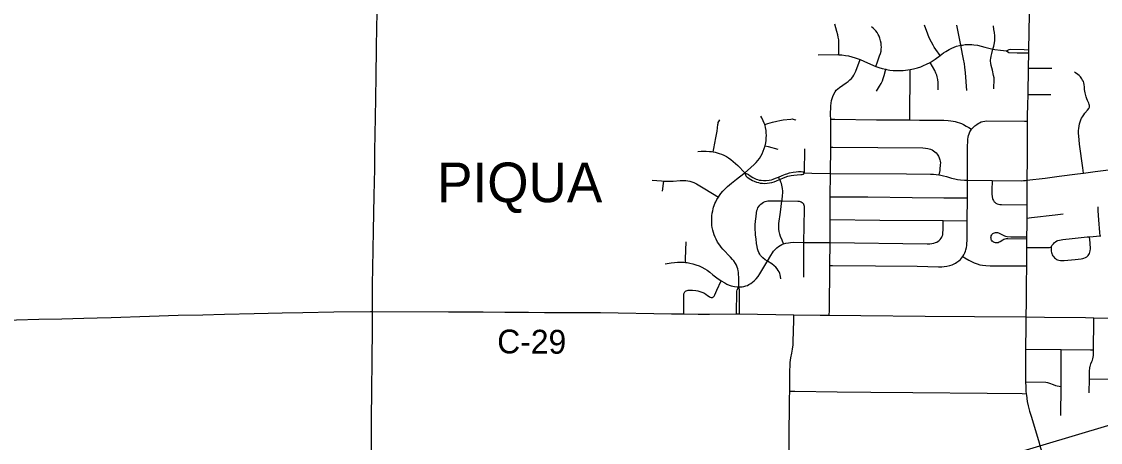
# Model space of a CAD drawing. Extents: x -87 to 2145, y -2128 to 440.
# Drawn here: x 86.3 to 154.2, y -1144.5 to -1118 of the extents above; entities that cross this region are included whole.
import ezdxf

# ---------------------------------------------------------------- set-up
doc = ezdxf.new("R2010")
doc.units = 0
for name, color, linetype in [('GM_X_City_Street', 7, 'Continuous'), ('GM_X_Corporation_Text', 7, 'Continuous'), ('GM_X_County_Road', 7, 'Continuous'), ('GM_X_County_Road_Text', 7, 'Continuous'), ('GM_X_Rail_Line', 7, 'Continuous'), ('GM_X_State_Route', 7, 'Continuous'), ('GM_X_Township_Road', 7, 'Continuous')]:
    doc.layers.add(name, color=color, linetype=linetype)

msp = doc.modelspace()

# ---------------------------------------------------------------- linework, layer by layer
at = {"layer": 'GM_X_City_Street'}
for p, q in [((145.448, -1119.471), (145.198, -1118.209)), ((142.232, -1124.177), (142.259, -1121)), ((135.603, -1127.502), (135.61, -1125.992))]:
    msp.add_line(p, q, dxfattribs=at)
for points in [[(137.759, -1120.066), (137.763, -1119.877), (137.766, -1119.652), (137.761, -1119.341), (137.747, -1119.13), (137.724, -1118.952), (137.693, -1118.808), (137.635, -1118.604), (137.503, -1118.149)], [(140.086, -1120.799), (140.196, -1120.507), (140.327, -1120.144), (140.381, -1119.994), (140.419, -1119.838), (140.432, -1119.721), (140.437, -1119.586), (140.429, -1119.461), (140.416, -1119.333), (140.389, -1119.19), (140.342, -1119.019), (140.297, -1118.898), (140.243, -1118.782), (140.177, -1118.672), (140.094, -1118.562), (140.011, -1118.479), (139.927, -1118.399), (139.82, -1118.312)], [(144.131, -1120.108), (143.855, -1119.731), (143.766, -1119.594), (143.688, -1119.47), (143.589, -1119.282), (143.455, -1119.001), (143.36, -1118.776), (143.144, -1118.206)], [(147.462, -1119.712), (147.524, -1119.524), (147.569, -1119.321), (147.585, -1119.16), (147.589, -1119.031), (147.58, -1118.869), (147.554, -1118.659), (147.523, -1118.481), (147.5, -1118.251)], [(136.449, -1120.065), (137.65, -1120.058), (137.759, -1120.066), (137.945, -1120.08), (138.175, -1120.108), (138.37, -1120.144), (138.578, -1120.195), (138.784, -1120.258), (139.107, -1120.375), (139.337, -1120.47), (139.754, -1120.665), (140.086, -1120.799), (140.272, -1120.864), (140.491, -1120.927), (140.709, -1120.979), (140.761, -1120.992), (140.97, -1121.028), (141.18, -1121.052), (141.376, -1121.062), (141.621, -1121.065), (141.816, -1121.055), (142.092, -1121.026), (142.259, -1121), (142.46, -1120.957), (142.713, -1120.89), (142.913, -1120.822), (143.095, -1120.751), (143.272, -1120.667), (143.501, -1120.546), (143.687, -1120.428), (143.815, -1120.339), (144.131, -1120.108), (144.345, -1119.95), (144.498, -1119.852), (144.713, -1119.729), (144.875, -1119.647), (145.028, -1119.582), (145.17, -1119.535), (145.347, -1119.49), (145.448, -1119.471), (145.542, -1119.454), (145.722, -1119.431), (145.904, -1119.421), (146.136, -1119.423), (146.268, -1119.436), (146.48, -1119.473), (146.722, -1119.524), (146.961, -1119.587), (147.462, -1119.712), (147.582, -1119.742), (147.938, -1119.786), (148.325, -1119.82)], [(145.828, -1122.316), (145.734, -1121.21), (145.698, -1120.852), (145.667, -1120.642), (145.618, -1120.337), (145.553, -1120.029), (145.448, -1119.471)], [(147.511, -1122.213), (147.52, -1122.028), (147.537, -1121.781), (147.54, -1121.638), (147.531, -1121.523), (147.504, -1121.378), (147.43, -1121.041), (147.361, -1120.753), (147.329, -1120.592), (147.316, -1120.477), (147.316, -1120.395), (147.326, -1120.297), (147.354, -1120.152), (147.397, -1119.993), (147.462, -1119.712)], [(148.325, -1119.82), (148.481, -1119.729), (148.563, -1119.721), (149.434, -1119.743), (149.709, -1119.75)], [(148.325, -1119.82), (148.468, -1119.92), (148.982, -1119.938), (149.455, -1119.941), (149.706, -1119.943)], [(137.157, -1136.48), (137.16, -1136.177), (137.187, -1133.356), (137.2, -1131.908), (137.213, -1130.458), (137.216, -1129.013), (137.229, -1127.556), (137.251, -1125.892), (137.242, -1124.131), (137.237, -1123.882), (137.253, -1123.291), (137.27, -1123.11), (137.298, -1122.946), (137.331, -1122.817), (137.369, -1122.707), (137.432, -1122.559), (137.517, -1122.41), (137.597, -1122.308), (137.702, -1122.208), (137.793, -1122.134), (138.219, -1121.837), (138.338, -1121.751), (138.448, -1121.657), (138.551, -1121.554), (138.634, -1121.455), (138.709, -1121.35), (138.774, -1121.236), (138.83, -1121.105), (139.107, -1120.375)], [(140.122, -1122.372), (140.319, -1122.052), (140.414, -1121.879), (140.497, -1121.7), (140.554, -1121.557), (140.611, -1121.372), (140.709, -1120.979)], [(144.003, -1122.286), (144.003, -1121.825), (143.983, -1121.621), (143.952, -1121.462), (143.923, -1121.349), (143.875, -1121.224), (143.796, -1121.059), (143.656, -1120.797), (143.501, -1120.546)], [(149.688, -1120.918), (149.881, -1120.919), (151.174, -1120.922)], [(153.158, -1127.522), (153.115, -1127.186), (152.923, -1125.694), (152.864, -1125.173), (152.849, -1125.026), (152.844, -1124.928), (152.851, -1124.831), (152.862, -1124.712), (152.884, -1124.577), (152.914, -1124.429), (152.949, -1124.299), (153.002, -1124.163), (153.046, -1124.058), (153.095, -1123.972), (153.181, -1123.852), (153.26, -1123.748), (153.411, -1123.554), (153.498, -1123.453), (153.539, -1123.379), (153.553, -1123.319), (153.549, -1123.261), (153.532, -1123.199), (153.495, -1123.108), (153.417, -1122.945), (153.372, -1122.84), (153.331, -1122.715), (153.269, -1122.46), (153.235, -1122.267), (153.219, -1122.104), (153.204, -1121.941), (153.183, -1121.828), (153.157, -1121.751), (153.113, -1121.663), (153.06, -1121.58), (152.967, -1121.466), (152.887, -1121.384), (152.8, -1121.31), (152.653, -1121.206), (152.596, -1121.174)], [(149.658, -1122.568), (149.938, -1122.567), (151.107, -1122.562)], [(131.452, -1134.698), (131.448, -1134.232), (131.427, -1133.775), (131.413, -1133.68), (131.386, -1133.567), (131.351, -1133.456), (131.305, -1133.336), (131.246, -1133.219), (131.139, -1133.056), (131.061, -1132.965), (130.931, -1132.818), (130.452, -1132.323), (130.345, -1132.2), (130.25, -1132.074), (130.123, -1131.877), (130.022, -1131.69), (129.966, -1131.569), (129.905, -1131.412), (129.86, -1131.272), (129.817, -1131.116), (129.786, -1130.951), (129.767, -1130.819), (129.755, -1130.62), (129.754, -1130.406), (129.764, -1130.224), (129.787, -1130.043), (129.814, -1129.901), (129.84, -1129.781), (129.869, -1129.674), (129.907, -1129.562), (129.951, -1129.449), (130.003, -1129.335), (130.078, -1129.192), (130.168, -1129.049), (130.237, -1128.946), (130.332, -1128.817), (130.458, -1128.664), (130.616, -1128.495), (130.747, -1128.369), (130.985, -1128.166), (131.308, -1127.912), (131.771, -1127.546), (131.828, -1127.499), (132.188, -1127.201), (132.443, -1126.972), (132.557, -1126.856), (132.661, -1126.732), (132.757, -1126.598), (132.845, -1126.458), (132.923, -1126.311), (132.998, -1126.143), (133.061, -1125.969), (133.111, -1125.799), (133.152, -1125.611), (133.174, -1125.461), (133.187, -1125.312), (133.192, -1125.163), (133.186, -1124.982), (133.171, -1124.835), (133.141, -1124.659), (133.107, -1124.517), (133.089, -1124.462), (133.062, -1124.379), (132.999, -1124.229), (132.904, -1124.04), (132.849, -1123.939)], [(129.846, -1126.19), (129.884, -1125.985), (130.012, -1125.293), (130.087, -1124.891), (130.133, -1124.468), (130.145, -1124.404), (130.163, -1124.342), (130.191, -1124.282), (130.256, -1124.169)], [(133.089, -1124.462), (133.275, -1124.403), (133.584, -1124.312), (133.844, -1124.247), (134.036, -1124.204), (134.254, -1124.165), (134.737, -1124.118), (134.819, -1124.114), (134.884, -1124.12), (134.947, -1124.137), (135.036, -1124.178), (135.051, -1124.185)], [(137.242, -1124.131), (137.512, -1124.134), (140.138, -1124.16), (142.232, -1124.177), (142.845, -1124.181), (144.378, -1124.186), (144.651, -1124.204), (144.816, -1124.221), (144.947, -1124.243), (145.09, -1124.273), (145.218, -1124.311), (145.361, -1124.355), (145.489, -1124.407), (145.618, -1124.471), (145.784, -1124.564), (145.942, -1124.658), (146.116, -1124.767)], [(146.116, -1124.767), (146.233, -1124.632), (146.321, -1124.555), (146.438, -1124.461), (146.534, -1124.395), (146.624, -1124.347), (146.727, -1124.302), (146.827, -1124.272), (146.961, -1124.251), (147.078, -1124.24), (149.443, -1124.251), (149.626, -1124.251)], [(145.562, -1132.791), (145.636, -1132.669), (145.688, -1132.561), (145.732, -1132.444), (145.761, -1132.359), (145.794, -1132.217), (145.813, -1132.089), (145.827, -1131.944), (145.838, -1131.794), (145.844, -1130.543), (145.851, -1129.084), (145.853, -1128.662), (145.864, -1127.971), (145.869, -1127.696), (145.865, -1125.972), (145.889, -1125.396), (145.904, -1125.264), (145.927, -1125.166), (145.965, -1125.055), (146.016, -1124.932), (146.059, -1124.854), (146.116, -1124.767)], [(133.111, -1125.799), (133.314, -1125.853), (133.909, -1126.01)], [(137.251, -1125.892), (137.385, -1125.893), (143.049, -1125.941), (143.214, -1125.949), (143.357, -1125.967), (143.449, -1125.988), (143.531, -1126.019), (143.627, -1126.067), (143.718, -1126.127), (143.8, -1126.184), (143.882, -1126.258), (143.949, -1126.325), (143.997, -1126.388), (144.037, -1126.456), (144.082, -1126.559), (144.127, -1126.696), (144.143, -1126.773), (144.15, -1126.869), (144.147, -1127.014), (144.123, -1127.274), (144.107, -1127.368), (144.064, -1127.631)], [(128.877, -1126.163), (129.089, -1126.148), (129.238, -1126.139), (129.404, -1126.142), (129.608, -1126.157), (129.738, -1126.174), (129.846, -1126.19), (129.966, -1126.213), (130.09, -1126.242), (130.218, -1126.281), (130.375, -1126.336), (130.512, -1126.396), (130.604, -1126.437), (130.688, -1126.486), (130.815, -1126.567), (130.952, -1126.661), (131.108, -1126.784), (131.256, -1126.916), (131.396, -1127.057), (131.828, -1127.499)], [(126.002, -1127.963), (126.581, -1128.021), (126.736, -1128.035), (127.034, -1128.039), (127.33, -1128.028), (127.756, -1127.997), (127.918, -1127.992), (128.113, -1128), (128.242, -1128.015), (128.369, -1128.039), (128.493, -1128.074), (128.63, -1128.126), (128.792, -1128.199), (128.906, -1128.261), (129.324, -1128.521), (130.168, -1129.049)], [(131.828, -1127.499), (132.061, -1127.609), (132.18, -1127.697), (132.345, -1127.804), (132.46, -1127.868), (132.55, -1127.908), (132.627, -1127.934), (132.739, -1127.961), (132.869, -1127.978), (133.017, -1127.986), (133.181, -1127.982), (133.377, -1127.964), (133.507, -1127.943), (133.617, -1127.912), (133.771, -1127.855), (133.948, -1127.777), (134.177, -1127.676), (134.291, -1127.626), (134.395, -1127.59), (134.483, -1127.564), (134.657, -1127.518), (134.882, -1127.471), (135.061, -1127.444), (135.224, -1127.432), (135.387, -1127.435), (135.499, -1127.443), (135.603, -1127.502)], [(131.828, -1127.499), (131.891, -1127.708), (131.987, -1127.79), (132.207, -1127.933), (132.322, -1127.996), (132.427, -1128.043), (132.566, -1128.092), (132.692, -1128.128), (132.805, -1128.15), (132.952, -1128.167), (133.099, -1128.172), (133.247, -1128.166), (133.393, -1128.148), (133.538, -1128.118), (133.679, -1128.076), (133.832, -1128.018), (134.028, -1127.928), (134.233, -1127.843), (134.38, -1127.784), (134.553, -1127.725), (134.745, -1127.68), (134.913, -1127.652), (135.125, -1127.63), (135.366, -1127.619), (135.453, -1127.613), (135.529, -1127.589), (135.603, -1127.502)], [(134.28, -1131.99), (134.183, -1131.745), (134.092, -1131.515), (134.048, -1131.372), (134.008, -1131.216), (133.982, -1131.063), (133.973, -1130.931), (133.972, -1130.83), (133.984, -1130.697), (134.077, -1129.997), (134.176, -1129.28), (134.185, -1129.216), (134.213, -1128.94), (134.222, -1128.778), (134.219, -1128.665), (134.21, -1128.505), (134.193, -1128.394), (134.17, -1128.294), (134.141, -1128.183), (134.106, -1128.091), (134.053, -1127.977), (134.028, -1127.928), (133.988, -1127.85), (133.948, -1127.777)], [(135.603, -1127.502), (136.046, -1127.538), (137.229, -1127.556), (142.01, -1127.577), (143.52, -1127.594), (143.728, -1127.596), (143.894, -1127.61), (144.064, -1127.631), (144.19, -1127.655), (144.346, -1127.694), (144.544, -1127.748), (144.858, -1127.841), (145.063, -1127.893), (145.239, -1127.925), (145.417, -1127.947), (145.678, -1127.964), (145.864, -1127.971), (147.405, -1127.996), (149.234, -1128.008), (149.386, -1127.999), (149.51, -1127.987), (149.606, -1127.973)], [(147.405, -1127.996), (147.391, -1128.626), (147.394, -1128.827), (147.409, -1129.017), (147.429, -1129.117), (147.453, -1129.182), (147.489, -1129.254), (147.542, -1129.328), (147.579, -1129.366), (147.653, -1129.416), (147.727, -1129.453), (147.808, -1129.482), (147.904, -1129.498), (148.004, -1129.507), (149.599, -1129.516)], [(126.648, -1128.672), (126.714, -1128.191), (126.736, -1128.035)], [(133.256, -1133.076), (133.123, -1132.986), (132.97, -1132.861), (132.897, -1132.795), (132.832, -1132.721), (132.776, -1132.645), (132.723, -1132.539), (132.674, -1132.417), (132.635, -1132.292), (132.604, -1132.148), (132.575, -1131.962), (132.539, -1131.659), (132.512, -1131.432), (132.497, -1131.271), (132.487, -1131.106), (132.481, -1130.926), (132.487, -1130.776), (132.509, -1130.554), (132.543, -1130.255), (132.576, -1130.03), (132.6, -1129.884), (132.627, -1129.79), (132.66, -1129.715), (132.711, -1129.631), (132.771, -1129.553), (132.841, -1129.484), (132.919, -1129.424), (133.018, -1129.366), (133.122, -1129.319), (133.2, -1129.294), (133.281, -1129.281), (133.421, -1129.276), (134.176, -1129.28), (135.182, -1129.287), (135.264, -1129.293), (135.327, -1129.308), (135.387, -1129.334), (135.442, -1129.37), (135.508, -1129.435)], [(137.216, -1129.013), (139.59, -1129.027), (142.379, -1129.053), (144.378, -1129.075), (145.851, -1129.084)], [(135.551, -1134.086), (135.561, -1131.892), (135.587, -1129.789), (135.585, -1129.641), (135.574, -1129.56), (135.56, -1129.513), (135.544, -1129.485), (135.508, -1129.435)], [(154.207, -1131.474), (154.189, -1131.266), (154.123, -1130.479), (154.101, -1130.191), (154.092, -1129.879), (154.092, -1129.649)], [(126.814, -1133.24), (127.186, -1133.18), (127.398, -1133.151), (127.594, -1133.136), (127.807, -1133.131), (128.003, -1133.14), (128.098, -1133.15), (128.199, -1133.161), (128.377, -1133.193), (128.551, -1133.237), (128.754, -1133.301), (128.954, -1133.377), (129.119, -1133.45), (129.321, -1133.558), (129.461, -1133.643), (129.634, -1133.773), (129.822, -1133.927), (130.081, -1134.127), (130.347, -1134.308), (130.565, -1134.436), (130.708, -1134.516), (130.841, -1134.578), (130.964, -1134.624), (131.075, -1134.654), (131.188, -1134.674), (131.357, -1134.698), (131.452, -1134.698), (131.531, -1134.698), (131.663, -1134.687), (131.776, -1134.669), (131.903, -1134.635), (131.994, -1134.601), (132.096, -1134.552), (132.206, -1134.484), (132.316, -1134.406), (132.423, -1134.318), (132.55, -1134.191), (132.671, -1134.038), (132.785, -1133.866), (133.222, -1133.134), (133.256, -1133.076), (133.473, -1132.711), (133.571, -1132.56), (133.651, -1132.455), (133.749, -1132.346), (133.855, -1132.243), (133.957, -1132.16), (134.066, -1132.088), (134.168, -1132.034), (134.28, -1131.99), (134.415, -1131.949), (134.575, -1131.913), (134.705, -1131.895), (134.885, -1131.886), (135.561, -1131.892), (137.2, -1131.908), (143.324, -1131.975), (143.49, -1131.973), (143.619, -1131.961), (143.729, -1131.94), (143.836, -1131.908), (143.927, -1131.869), (144.011, -1131.82), (144.076, -1131.769), (144.146, -1131.7), (144.197, -1131.636), (144.239, -1131.566), (144.273, -1131.491), (144.297, -1131.413), (144.312, -1131.316), (144.325, -1131.07), (144.326, -1130.742), (144.327, -1130.523)], [(137.213, -1130.458), (140.333, -1130.486), (144.327, -1130.523), (145.844, -1130.543)], [(149.591, -1130.364), (149.896, -1130.327), (151.374, -1130.149), (151.879, -1130.09)], [(149.582, -1131.693), (148.404, -1131.666), (148.29, -1131.674), (148.209, -1131.688), (148.147, -1131.709), (148.075, -1131.746), (147.925, -1131.848), (147.854, -1131.888), (147.793, -1131.912), (147.746, -1131.924), (147.68, -1131.929), (147.615, -1131.922), (147.552, -1131.904), (147.508, -1131.883), (147.468, -1131.855), (147.419, -1131.812), (147.377, -1131.753), (147.353, -1131.702), (147.342, -1131.648), (147.336, -1131.597), (147.341, -1131.536), (147.36, -1131.475), (147.385, -1131.423), (147.423, -1131.372), (147.459, -1131.339), (147.501, -1131.313), (147.562, -1131.288), (147.626, -1131.273), (147.691, -1131.269), (147.756, -1131.276), (147.819, -1131.293), (147.895, -1131.325), (148.065, -1131.422), (148.185, -1131.476), (148.263, -1131.5), (148.36, -1131.518), (148.588, -1131.539), (149.227, -1131.545), (149.583, -1131.548)], [(128.098, -1133.15), (128.104, -1132.93), (128.133, -1131.85)], [(149.578, -1132.21), (149.939, -1132.209), (150.199, -1132.208), (150.375, -1132.207), (150.659, -1132.21), (150.936, -1132.211), (151.033, -1132.205), (151.125, -1132.192), (151.18, -1132.096), (151.273, -1131.975), (151.344, -1131.903), (151.407, -1131.848), (151.48, -1131.801), (151.559, -1131.769), (151.658, -1131.744), (151.855, -1131.715), (152.457, -1131.656), (153.401, -1131.551), (153.542, -1131.537), (154.207, -1131.474), (154.249, -1131.47)], [(151.125, -1132.192), (151.137, -1132.441), (151.146, -1132.525), (151.163, -1132.592), (151.196, -1132.671), (151.239, -1132.745), (151.29, -1132.811), (151.348, -1132.874), (151.401, -1132.918), (151.473, -1132.963), (151.536, -1132.991), (151.617, -1133.015), (151.717, -1133.033), (151.802, -1133.038), (151.957, -1133.032), (152.648, -1132.975), (152.836, -1132.958), (153.012, -1132.936), (153.114, -1132.912), (153.187, -1132.889), (153.288, -1132.846), (153.367, -1132.798), (153.422, -1132.756), (153.458, -1132.72), (153.499, -1132.664), (153.539, -1132.588), (153.569, -1132.506), (153.589, -1132.42), (153.605, -1132.299), (153.603, -1132.214), (153.587, -1132.033), (153.576, -1131.919), (153.542, -1131.537)], [(134.097, -1134.182), (134.083, -1134.037), (134.065, -1133.943), (134.037, -1133.852), (133.991, -1133.751), (133.933, -1133.654), (133.867, -1133.563), (133.783, -1133.461), (133.676, -1133.367), (133.538, -1133.254), (133.432, -1133.18), (133.377, -1133.147), (133.256, -1133.076)], [(137.187, -1133.356), (137.363, -1133.358), (140.055, -1133.379), (142.697, -1133.4), (144.027, -1133.424), (144.239, -1133.426), (144.384, -1133.415), (144.56, -1133.394), (144.742, -1133.355), (144.89, -1133.303), (145.011, -1133.251), (145.094, -1133.203), (145.185, -1133.142), (145.311, -1133.051), (145.41, -1132.964), (145.489, -1132.882), (145.562, -1132.791)], [(145.562, -1132.791), (145.688, -1132.869), (145.943, -1133.019), (146.105, -1133.104), (146.286, -1133.184), (146.474, -1133.253), (146.632, -1133.3), (146.796, -1133.327), (147.009, -1133.352), (147.289, -1133.367), (147.551, -1133.37), (149.242, -1133.371), (149.566, -1133.372)], [(127.985, -1136.401), (127.987, -1136.283), (127.984, -1135.201), (127.992, -1135.136), (128.007, -1135.09), (128.03, -1135.046), (128.061, -1135.008), (128.097, -1134.975), (128.139, -1134.949), (128.2, -1134.925), (128.264, -1134.911), (128.346, -1134.908), (128.543, -1134.913), (128.739, -1134.93), (128.885, -1134.952), (128.996, -1134.98), (129.136, -1135.028), (129.255, -1135.082), (129.369, -1135.148), (129.488, -1135.235), (129.582, -1135.301), (129.654, -1135.34), (129.716, -1135.363), (129.764, -1135.367), (129.796, -1135.361), (129.826, -1135.349), (129.866, -1135.319), (129.898, -1135.282), (129.947, -1135.197), (130.075, -1134.912), (130.347, -1134.308)], [(131.318, -1136.404), (131.328, -1134.97), (131.352, -1134.883), (131.452, -1134.698)], [(131.489, -1136.403), (131.501, -1134.977), (131.495, -1134.874), (131.452, -1134.698)], [(134.561, -1153.375), (134.574, -1149.5), (134.576, -1149.373), (134.59, -1148.286), (134.605, -1146.908), (134.628, -1144.432), (134.656, -1141.741), (134.659, -1141.274), (134.662, -1140.841), (134.659, -1140.463), (134.666, -1140.019), (134.682, -1139.638), (134.699, -1139.456), (134.741, -1139.159), (134.793, -1138.883), (134.844, -1138.612), (134.872, -1138.357), (134.883, -1138.164), (134.912, -1136.803), (134.92, -1136.448)], [(153.527, -1141.375), (153.536, -1140.5), (153.539, -1140.26), (153.551, -1139.965), (153.56, -1139.839), (153.571, -1139.759), (153.58, -1139.712), (153.6, -1139.633), (153.631, -1139.539), (153.689, -1139.406), (153.728, -1139.319), (153.757, -1139.229), (153.778, -1139.135), (153.794, -1139.024), (153.803, -1138.878), (153.805, -1138.725), (153.806, -1138.662), (153.818, -1136.844), (153.819, -1136.641)], [(149.523, -1138.617), (151.767, -1138.64), (153.61, -1138.66), (153.806, -1138.662)], [(151.731, -1142.812), (151.751, -1140.981), (151.767, -1138.64)], [(149.515, -1140.673), (150.802, -1140.706), (150.896, -1140.718), (150.957, -1140.734), (151.032, -1140.759), (151.256, -1140.857), (151.41, -1140.915), (151.507, -1140.942), (151.751, -1140.981)], [(153.536, -1140.5), (155.686, -1140.517), (155.951, -1140.509), (156.035, -1140.504), (156.106, -1140.49), (156.185, -1140.466), (156.328, -1140.415), (156.495, -1140.345), (156.556, -1140.323), (156.634, -1140.303), (156.729, -1140.287), (156.84, -1140.28), (157.455, -1140.289), (158.165, -1140.305), (158.588, -1140.331), (158.799, -1140.348), (159.338, -1140.392), (159.577, -1140.405), (160.125, -1140.417), (160.403, -1140.419)], [(134.659, -1141.274), (134.988, -1141.278), (137.658, -1141.313), (139.774, -1141.336), (142.421, -1141.36), (147.089, -1141.401), (149.295, -1141.425), (149.559, -1141.428)]]:
    msp.add_lwpolyline(points, dxfattribs=at)
at = {"layer": 'GM_X_County_Road'}
for p, q in [((122.353, -1136.309), (122.75, -1136.316)), ((149.541, -1136.594), (150.701, -1136.607)), ((153.819, -1136.641), (155.638, -1136.664))]:
    msp.add_line(p, q, dxfattribs=at)
for points in [[(153.158, -1127.522), (153.9, -1127.424), (154.568, -1127.342), (155.014, -1127.287)], [(149.606, -1127.973), (150.748, -1127.836), (151.643, -1127.724), (152.781, -1127.572), (153.158, -1127.522)], [(82.272, -1136.857), (83.455, -1136.837), (84.537, -1136.813), (87.372, -1136.739), (88.807, -1136.702), (90.193, -1136.677), (91.046, -1136.652), (91.927, -1136.622), (94.34, -1136.539), (96.135, -1136.485), (97.689, -1136.448), (99.056, -1136.413), (100.938, -1136.374), (102.691, -1136.339), (103.997, -1136.32), (105.942, -1136.274), (108.249, -1136.251), (108.38, -1136.249)], [(108.38, -1136.249), (113.164, -1136.261), (115.33, -1136.273), (115.356, -1136.273)], [(115.356, -1136.273), (116.717, -1136.289), (118.21, -1136.298), (119.226, -1136.302), (122.353, -1136.309)], [(122.75, -1136.316), (127.218, -1136.392), (127.985, -1136.401)], [(127.985, -1136.401), (128.892, -1136.411), (129.614, -1136.414), (131.318, -1136.404)], [(131.318, -1136.404), (131.489, -1136.403), (134.92, -1136.448)], [(134.92, -1136.448), (136.581, -1136.474), (137.157, -1136.48)], [(137.157, -1136.48), (139.141, -1136.5), (143.194, -1136.537), (146.295, -1136.565), (149.541, -1136.594)], [(150.701, -1136.607), (153.285, -1136.634), (153.819, -1136.641)]]:
    msp.add_lwpolyline(points, dxfattribs=at)
at = {"layer": 'GM_X_Rail_Line'}
msp.add_lwpolyline([(32.645, -1179.993), (33.938, -1179.677), (35.52, -1179.34), (58.27, -1172.536), (79.726, -1166.155), (101.875, -1159.348), (126.551, -1151.893), (148.59, -1145.271), (154.705, -1143.429), (159.327, -1142.564), (162.774, -1141.883), (166.327, -1141.143), (170.107, -1140.276), (172.235, -1139.734), (175.075, -1139.439), (176.226, -1139.455)], dxfattribs=at)
at = {"layer": 'GM_X_State_Route'}
for points in [[(149.756, -1117.113), (149.75, -1117.512), (149.709, -1119.75), (149.706, -1119.943), (149.689, -1120.886), (149.688, -1120.918), (149.658, -1122.568), (149.646, -1123.246), (149.627, -1123.9), (149.626, -1124.251), (149.623, -1124.997), (149.617, -1125.865), (149.608, -1126.603), (149.606, -1127.973)], [(149.606, -1127.973), (149.599, -1129.516), (149.591, -1130.364), (149.587, -1130.814), (149.583, -1131.548), (149.582, -1131.693), (149.579, -1132.027), (149.578, -1132.21), (149.566, -1133.372), (149.554, -1134.55), (149.551, -1135.631), (149.541, -1136.594)], [(149.541, -1136.594), (149.535, -1137.173), (149.523, -1138.617), (149.523, -1138.961), (149.513, -1140.222), (149.515, -1140.673), (149.524, -1140.997), (149.542, -1141.262), (149.559, -1141.428), (149.569, -1141.525), (149.628, -1141.919), (149.686, -1142.191), (149.774, -1142.532), (149.864, -1142.846), (150.013, -1143.335), (150.372, -1144.526), (150.401, -1144.624), (150.904, -1146.253), (151.555, -1148.435)]]:
    msp.add_lwpolyline(points, dxfattribs=at)
at = {"layer": 'GM_X_Township_Road'}
for points in [[(108.38, -1136.249), (108.376, -1135.834), (108.393, -1134.529), (108.408, -1133.512), (108.453, -1131.159), (108.495, -1128.946), (108.525, -1127.253), (108.54, -1126.124), (108.579, -1124.011), (108.592, -1122.793), (108.61, -1121.422), (108.631, -1119.681), (108.657, -1118.279), (108.716, -1115.99), (108.763, -1113.992), (108.779, -1113.156), (108.846, -1110.369), (108.852, -1110.052)], [(108.253, -1149.476), (108.265, -1148.889), (108.262, -1148.138), (108.276, -1146.838), (108.291, -1145.918), (108.31, -1144.306), (108.319, -1142.585), (108.332, -1141.65), (108.36, -1138.913), (108.373, -1137.728), (108.382, -1136.4), (108.38, -1136.249)]]:
    msp.add_lwpolyline(points, dxfattribs=at)

# ---------------------------------------------------------------- texts
at = {"layer": 'GM_X_Corporation_Text'}
msp.add_text('PIQUA', height=2.5, rotation=0.00001, dxfattribs=at).set_placement((112.453, -1129.361))
at = {"layer": 'GM_X_County_Road_Text'}
msp.add_text('C-29', height=1.5, rotation=359.65526, dxfattribs=at).set_placement((116.234, -1138.885))

doc.saveas('drawing.dxf')
